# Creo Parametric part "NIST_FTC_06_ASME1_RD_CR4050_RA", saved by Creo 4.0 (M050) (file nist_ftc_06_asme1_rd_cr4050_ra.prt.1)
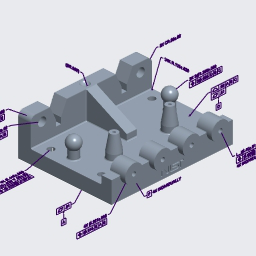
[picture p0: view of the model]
Units: Inch lbm Second (Pro/E Default); INCH, POUND, SECS

Created from: NIST_FTC_06_CREO4M020_SA_ANNOT.PRT

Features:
  1. datum plane "RIGHT"
  2. datum plane "TOP"
  3. datum plane "FRONT"
  4. coordinate system
  5. protrusion
  6. datum plane "MIDPLANE"
  7. pattern
  8. protrusion
  9. protrusion
  10. protrusion
  11. protrusion
  12. cut
  13. curve
  14. curve
  15. datum plane "MIDPLANE_DTM_J"
  16. cut
  17. curve
  18. curve
  19. datum plane "MIDPLANE_DTM_K"
  20. datum plane "CONE_CENTERS"
  21. protrusion
  22. hole
  23. protrusion
  24. hole
  25. datum plane "SPHERE_CENTERS"
  26. protrusion
  27. protrusion
  28. pattern
  29. hole
  30. hole
  31. hole
  32. hole
  33. hole
  34. hole
  35. pattern
  36. hole
  37. hole
  38. hole
  39. hole
  40. cut
  41. round
  42. round
  43. datum plane "CONE_GAGE_HEIGHT"
  44. curve
  45. annotation "Annotation 3"
  46. annotation "Annotation 4"
  47. annotation "Annotation 5"
  48. annotation "Annotation 6"
  49. extruded cut "Extrude 4"
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
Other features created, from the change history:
  group "COPIED_GROUP_2"

Other named items: LOCAL_GROUP, LOCAL_GROUP_1, COPIED_GROUP_1, CONE_GAGE_CIRCLES, COPIED_GROUP, CONICAL_TAPER, FLAT_TAPER, DTM_TGT_G, DTM_TGT_H, REF_DIM_DTM_TGT_J, REF_DIM_DTM_TGT_K, CS0, CS1, CS2, CS3, CS4, CS5, CS6, CS7, CS8, CS9, CS10, CS11, CS12, CS13, GP0, DATUM_TAG_A, DRF1, GP2, DRF2, DATUM_TAG_C, GP3, DRF3, GP4, GP5, DATUM_TAG_D, AD136, GP6, DRF4, AD137, AD138, AD140, GP7, AD141, GP8, DRF5, AD142, AD144, GP9, GP10, GP11, DATUM_TAG_E, GP12, DRF6, GP13, GP14, AD145, GP16, DRF7, DATUM_TAG_F, AD146, AD148, GP17, DRF8, RD1, DATUM_TAG_G, AD151, AD153, GP18, DRF9, RD3, DATUM_TAG_H, AD154, AD156, GP19, DRF10, AD159, DATUM_TAG_J, DT2, DT3, GP20, DRF11, GP21, AD170, DATUM_TAG_K, DT4, DT5, GP22, DRF12, AE_NOTE0, AE_NOTE1, GP23, AD171, AD172, RD7, AE_DTM_TARGET1, AE_DTM_TARGET2, AE_REFERENCE_DIM0, AE_REFERENCE_DIM1, , AD177, GP25, DATUM_TAG_B, MBD_A, MBD_B, MBD_C, ANNOT_LAYER_STATE0001, ANNOT_LAYER_STATE0002, ANNOT_LAYER_STATE0003

Layers: ALL_ANNOTATIONS, ALL_AXES, ALL_CSYS, ALL_CURVES, ALL_PLANES, ALL_POINTS, ALL_QUILTS, DEF_CSYS, DEF_PLANES

Notes: �⏥ | .01 | �⏊ | .012 | A | B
